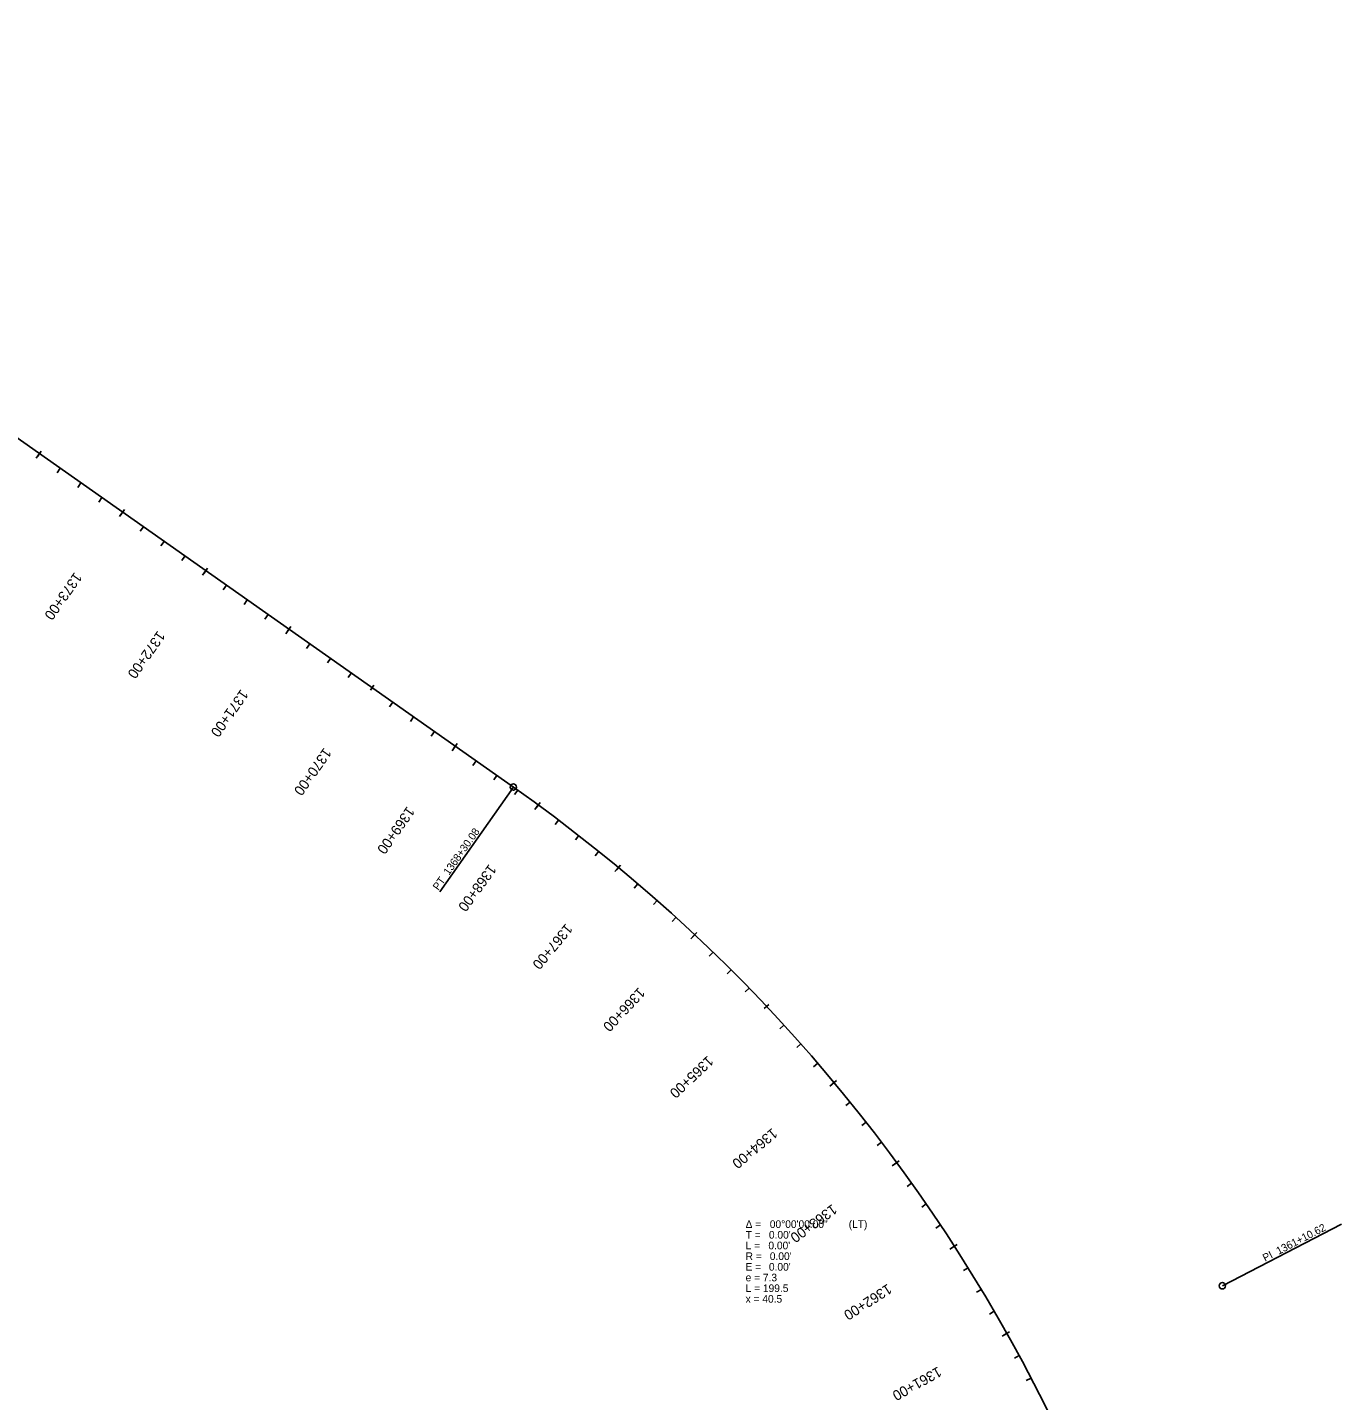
# Model space of a CAD drawing. Extents: x 14541681 to 14544384, y 8572153 to 8583558.
# Drawn here: x 14543091 to 14544383, y 8577856 to 8579206 of the extents above; entities that cross this region are included whole.
import ezdxf

# ---------------------------------------------------------------- set-up
doc = ezdxf.new("R2010")
doc.units = 0
for name, color, linetype in [('Alignment', 7, 'Continuous'), ('TextAlignment', 7, 'Continuous'), ('TextAlignmentLrg', 7, 'Continuous'), ('TextAlignmentSml', 7, 'Continuous')]:
    doc.layers.add(name, color=color, linetype=linetype)

msp = doc.modelspace()

# ---------------------------------------------------------------- linework, layer by layer
at = {"layer": 'Alignment'}
msp.add_line((14543568.7, 8578459.3), (14542506.7, 8579206.3), dxfattribs=at)
msp.add_arc((14542626.8, 8577120.2), 1637.1, 359.8604, 54.877, dxfattribs=at)
at = {"layer": 'TextAlignment'}
for p, q in [((14543568.7, 8578459.3), (14543496.2, 8578356.2)), ((14543496.2, 8578356.2), (14543496.2, 8578356.2)), ((14544266, 8577968.8), (14544383.2, 8578029.5)), ((14544383.2, 8578029.5), (14544383.2, 8578029.5))]:
    msp.add_line(p, q, dxfattribs=at)
for centre in [(14543568.7, 8578459.3), (14544266, 8577968.8)]:
    msp.add_circle(centre, 3.12, dxfattribs=at)
at = {"layer": 'TextAlignmentLrg'}
for p, q in [((14543102.6, 8578787.2), (14543099.4, 8578782.7)), ((14543184.3, 8578729.6), (14543181.2, 8578725.2)), ((14543266.1, 8578672.1), (14543263, 8578667.6)), ((14543347.9, 8578614.6), (14543344.8, 8578610.1)), ((14543428, 8578554.5), (14543431.5, 8578559.5)), ((14543511.5, 8578499.5), (14543508.4, 8578495)), ((14543593.1, 8578441.7), (14543589.9, 8578437.3)), ((14543672, 8578380.3), (14543668.5, 8578376.1)), ((14543747, 8578314.1), (14543743.2, 8578310.1)), ((14543815.5, 8578241.4), (14543820, 8578245.6)), ((14543884.1, 8578168.7), (14543879.9, 8578165.2)), ((14543945.8, 8578090), (14543941.4, 8578086.8)), ((14544002.5, 8578007.7), (14543997.9, 8578004.7)), ((14544054.1, 8577922), (14544049.4, 8577919.4))]:
    msp.add_line(p, q, dxfattribs=at)
at = {"layer": 'TextAlignmentSml'}
for p, q in [((14543100.8, 8578784.6), (14543104.3, 8578789.7)), ((14543123, 8578772.8), (14543119.9, 8578768.3)), ((14543143.4, 8578758.4), (14543140.3, 8578753.9)), ((14543163.9, 8578744), (14543160.8, 8578739.5)), ((14543182.6, 8578727.1), (14543186.1, 8578732.1)), ((14543204.8, 8578715.2), (14543201.6, 8578710.8)), ((14543225.2, 8578700.9), (14543222.1, 8578696.4)), ((14543245.7, 8578686.5), (14543242.5, 8578682)), ((14543264.4, 8578669.6), (14543267.9, 8578674.6)), ((14543286.6, 8578657.7), (14543283.4, 8578653.2)), ((14543307, 8578643.3), (14543303.9, 8578638.9)), ((14543327.5, 8578628.9), (14543324.3, 8578624.5)), ((14543346.2, 8578612), (14543349.7, 8578617.1)), ((14543368.4, 8578600.2), (14543365.2, 8578595.7)), ((14543388.8, 8578585.8), (14543385.7, 8578581.3)), ((14543409.3, 8578571.4), (14543406.1, 8578566.9)), ((14543428, 8578554.5), (14543431.5, 8578559.5)), ((14543450.2, 8578542.6), (14543447, 8578538.2)), ((14543470.6, 8578528.3), (14543467.5, 8578523.8)), ((14543491.1, 8578513.9), (14543487.9, 8578509.4)), ((14543509.8, 8578497), (14543513.3, 8578502)), ((14543532, 8578485.1), (14543528.8, 8578480.6)), ((14543552.4, 8578470.7), (14543549.3, 8578466.3)), ((14543572.9, 8578456.3), (14543569.7, 8578451.9)), ((14543591.3, 8578439.3), (14543594.9, 8578444.2)), ((14543613.2, 8578426.8), (14543609.9, 8578422.5)), ((14543633, 8578411.6), (14543629.7, 8578407.3)), ((14543652.6, 8578396.1), (14543649.2, 8578391.8)), ((14543670.1, 8578377.9), (14543674, 8578382.6)), ((14543691.1, 8578364.2), (14543687.6, 8578360)), ((14543710, 8578347.8), (14543706.4, 8578343.7)), ((14543728.6, 8578331.1), (14543724.9, 8578327)), ((14543744.9, 8578311.9), (14543749.1, 8578316.4)), ((14543765.1, 8578296.9), (14543761.3, 8578293)), ((14543782.9, 8578279.4), (14543779.1, 8578275.5)), ((14543800.5, 8578261.6), (14543796.6, 8578257.8)), ((14543815.5, 8578241.4), (14543820, 8578245.6)), ((14543834.8, 8578225.2), (14543830.8, 8578221.5)), ((14543851.5, 8578206.6), (14543847.4, 8578203)), ((14543868, 8578187.8), (14543863.8, 8578184.2)), ((14543881.8, 8578166.8), (14543886.5, 8578170.7)), ((14543900, 8578149.4), (14543895.7, 8578146)), ((14543915.6, 8578129.8), (14543911.3, 8578126.5)), ((14543930.8, 8578110), (14543926.5, 8578106.7)), ((14543943.3, 8578088.2), (14543948.2, 8578091.8)), ((14543960.4, 8578069.8), (14543956, 8578066.6)), ((14543974.8, 8578049.3), (14543970.3, 8578046.2)), ((14543988.8, 8578028.6), (14543984.3, 8578025.6)), ((14544000, 8578006), (14544005.1, 8578009.3)), ((14544015.9, 8577986.6), (14544011.3, 8577983.7)), ((14544029, 8577965.3), (14544024.3, 8577962.4)), ((14544041.7, 8577943.7), (14544037, 8577941)), ((14544051.5, 8577920.5), (14544056.8, 8577923.5)), ((14544066.2, 8577900.2), (14544061.4, 8577897.6)), ((14544077.9, 8577878.1), (14544073.1, 8577875.6))]:
    msp.add_line(p, q, dxfattribs=at)

# ---------------------------------------------------------------- texts
at = {"layer": 'TextAlignment'}
for s, rotation, p in [('1368+30.08', 54.877, (14543505.3, 8578372)), ('PT', 54.877, (14543494.9, 8578357.1)), ('1361+10.62', 27.3687, (14544321.3, 8577999.2)), ('PI ', 27.3687, (14544308, 8577992.4))]:
    msp.add_text(s, height=7.5, rotation=rotation, dxfattribs=at).set_placement(p)
for s, p in [('Δ = ', (14543797.1, 8578025.7)), ('00°00\'00.00"', (14543820.9, 8578025.7)), (' (LT)', (14543895.7, 8578025.7)), ('T = ', (14543797.1, 8578015.2)), ("0.00'", (14543820, 8578015.2)), ('L = ', (14543797.1, 8578004.7)), ("0.00'", (14543819.5, 8578004.7)), ('R = ', (14543797.1, 8577994.2)), ('E = ', (14543797.1, 8577983.7)), ("0.00'", (14543820, 8577983.7)), ("0.00'", (14543820.9, 8577994.2)), ('e = 7.3', (14543797.1, 8577973.2)), ('L = 199.5', (14543797.1, 8577962.7)), ('x = 40.5', (14543797.1, 8577952.2))]:
    msp.add_text(s, height=7.5, dxfattribs=at).set_placement(p)
at = {"layer": 'TextAlignmentLrg'}
for s, rotation, p in [('1370+00', 234.877, (14543382.5, 8578498.6)), ('1365+00', 223.3248, (14543759.8, 8578195.7))]:
    msp.add_text(s, height=10.02, rotation=rotation, dxfattribs=at).set_placement(p)
at = {"layer": 'TextAlignmentSml'}
for s, rotation, p in [('1373+00', 234.877, (14543137.1, 8578671.2)), ('1372+00', 234.877, (14543218.9, 8578613.6)), ('1371+00', 234.877, (14543300.7, 8578556.1)), ('1370+00', 234.877, (14543382.5, 8578498.6)), ('1369+00', 234.877, (14543464.3, 8578441)), ('1368+00', 233.8243, (14543544.8, 8578384.1)), ('1367+00', 230.3244, (14543620.3, 8578325.7)), ('1366+00', 226.8246, (14543692, 8578262.9)), ('1365+00', 223.3248, (14543759.8, 8578195.7)), ('1364+00', 219.8249, (14543823.3, 8578124.5)), ('1363+00', 216.3251, (14543882.4, 8578049.6)), ('1362+00', 212.8253, (14543936.8, 8577971.2)), ('1361+00', 209.3254, (14543986.3, 8577889.7))]:
    msp.add_text(s, height=10.02, rotation=rotation, dxfattribs=at).set_placement(p)

doc.saveas('drawing.dxf')
